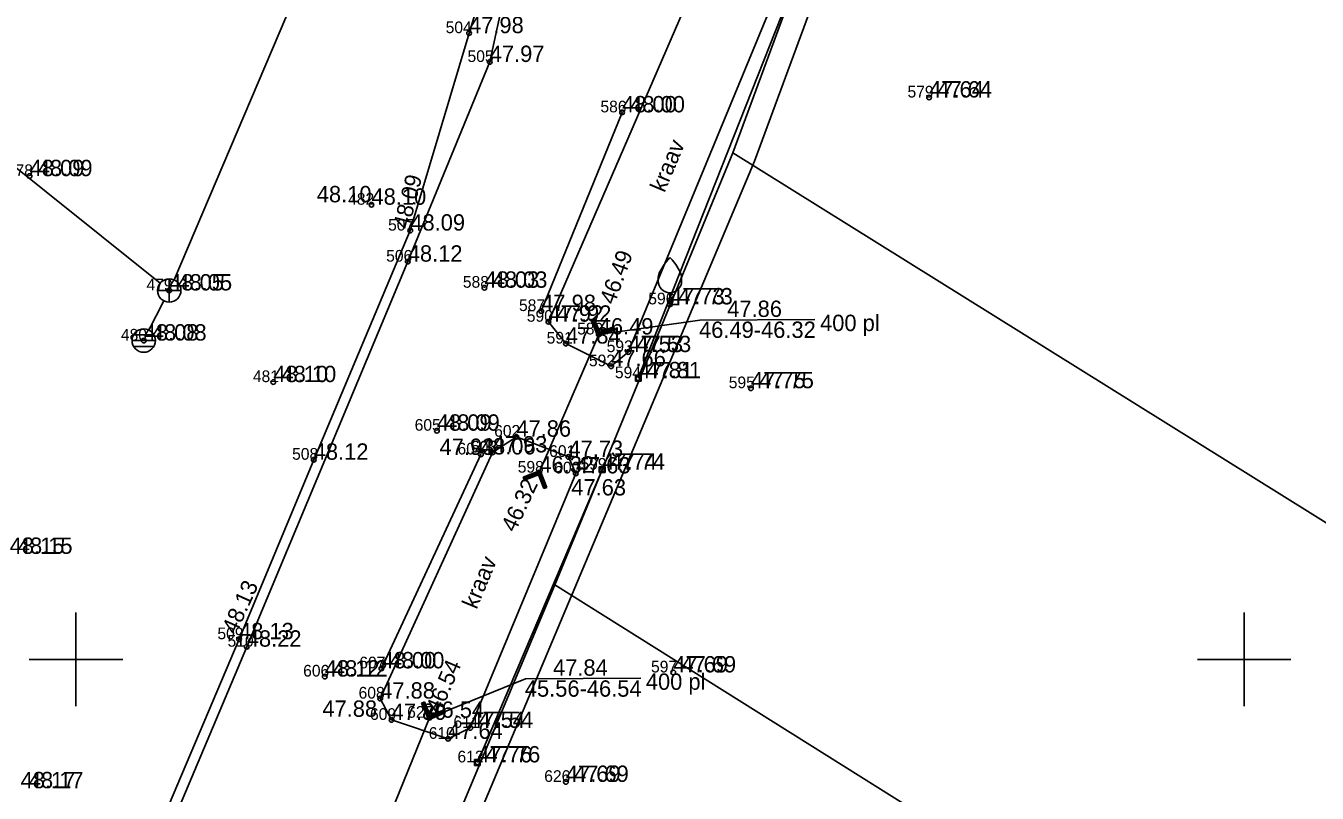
# Model space of a CAD drawing. Extents: x 640876 to 641418, y 6455595 to 6456085.
# Drawn here: x 641197.9 to 641253.1, y 6455944.3 to 6455977.1 of the extents above; entities that cross this region are included whole.
import ezdxf

# ---------------------------------------------------------------- set-up
doc = ezdxf.new("R2010")
doc.units = 0
for name, color, linetype in [('AED', 7, 'Continuous'), ('KKAEV', 7, 'Continuous'), ('KORGUS', 7, 'Continuous'), ('MOOTKORG', 7, 'Continuous'), ('MOOTMPUNKT', 7, 'Continuous'), ('MOOTNR', 7, 'Continuous'), ('MOOTPIIR', 7, 'Continuous'), ('PIIR', 7, 'Continuous'), ('PUU', 7, 'Continuous'), ('SKKAEV', 7, 'Continuous'), ('SKTRASS', 7, 'Continuous'), ('TEE', 7, 'Continuous'), ('TRUUP', 7, 'Continuous'), ('VEEKOGU', 7, 'Continuous'), ('VORK', 7, 'Continuous')]:
    doc.layers.add(name, color=color, linetype=linetype)

msp = doc.modelspace()

# ---------------------------------------------------------------- linework, layer by layer
at = {"layer": 'AED'}
for p, q in [((641223.94, 6455962.153), (641223.94, 6455961.903)), ((641223.94, 6455962.153), (641224.19, 6455962.153)), ((641223.94, 6455961.903), (641224.19, 6455961.903)), ((641224.19, 6455962.153), (641224.19, 6455961.903)), ((641222.394, 6455958.241), (641222.394, 6455957.991)), ((641222.394, 6455958.241), (641222.644, 6455958.241)), ((641222.644, 6455958.241), (641222.644, 6455957.991)), ((641222.394, 6455957.991), (641222.644, 6455957.991)), ((641217.053, 6455945.714), (641217.053, 6455945.464)), ((641217.053, 6455945.714), (641217.303, 6455945.714)), ((641217.053, 6455945.464), (641217.303, 6455945.464)), ((641217.303, 6455945.714), (641217.303, 6455945.464))]:
    msp.add_line(p, q, dxfattribs=at)
for points in [[(641160.606, 6455994.253), (641178.047, 6455995.168), (641191.652, 6455995.856), (641207.752, 6455996.687), (641222.341, 6455997.449), (641221.765, 6455994.718), (641219.959, 6455985.906), (641217.708, 6455975.561), (641214.2, 6455967.017), (641207.311, 6455950.541), (641202.719, 6455939.647), (641198.916, 6455930.446)], [(641231.229, 6455980.143), (641224.065, 6455962.028)], [(641222.519, 6455958.116), (641217.178, 6455945.589)]]:
    msp.add_lwpolyline(points, dxfattribs=at)
at = {"layer": 'KKAEV'}
for p, q in [((641203.491, 6455965.784), (641204.491, 6455965.784)), ((641203.991, 6455965.284), (641203.991, 6455966.284))]:
    msp.add_line(p, q, dxfattribs=at)
msp.add_circle((641203.991, 6455965.784), 0.5, dxfattribs=at)
at = {"layer": 'KORGUS'}
for centre in [(641236.513, 6455974.041), (641223.371, 6455973.405), (641198.016, 6455970.676), (641212.648, 6455969.453), (641214.309, 6455968.346), (641203.991, 6455965.784), (641217.483, 6455965.901), (641225.419, 6455965.189), (641220.221, 6455964.447), (641202.898, 6455963.64), (641222.374, 6455963.901), (641223.639, 6455963.147), (641208.446, 6455961.862), (641224.065, 6455962.028), (641228.888, 6455961.601), (641215.445, 6455959.783), (641217.83, 6455958.854), (641219.83, 6455957.988), (641221.392, 6455957.955), (641222.519, 6455958.116), (641206.979, 6455950.86), (641213.075, 6455949.614), (641210.648, 6455949.263), (641225.561, 6455949.439), (641213.02, 6455948.32), (641215.125, 6455947.499), (641216.876, 6455947.066), (641217.178, 6455945.589), (641220.966, 6455944.755)]:
    msp.add_circle(centre, 0.1, dxfattribs=at)
at = {"layer": 'MOOTMPUNKT'}
for centre in [(641216.822, 6455976.794), (641217.708, 6455975.561), (641236.513, 6455974.041), (641223.371, 6455973.405), (641198.016, 6455970.676), (641212.648, 6455969.453), (641214.309, 6455968.346), (641214.2, 6455967.017), (641203.991, 6455965.784), (641217.483, 6455965.901), (641225.419, 6455965.189), (641219.911, 6455964.904), (641220.221, 6455964.447), (641202.898, 6455963.64), (641220.969, 6455963.511), (641222.374, 6455963.901), (641223.639, 6455963.147), (641222.903, 6455962.539), (641208.446, 6455961.862), (641224.065, 6455962.028), (641228.888, 6455961.601), (641215.445, 6455959.783), (641218.847, 6455959.527), (641210.175, 6455958.541), (641217.328, 6455958.767), (641217.83, 6455958.854), (641221.076, 6455958.662), (641219.83, 6455957.988), (641221.392, 6455957.955), (641222.519, 6455958.116), (641206.979, 6455950.86), (641207.311, 6455950.541), (641213.075, 6455949.614), (641210.648, 6455949.263), (641225.561, 6455949.439), (641213.02, 6455948.32), (641213.509, 6455947.407), (641215.125, 6455947.499), (641216.876, 6455947.066), (641215.924, 6455946.598), (641217.178, 6455945.589), (641220.966, 6455944.755)]:
    msp.add_circle(centre, 0.1, dxfattribs=at)
at = {"layer": 'MOOTPIIR'}
msp.add_lwpolyline([(641060.916, 6455895.936), (641100.061, 6455950.482), (641099.586, 6455952.159), (641069.132, 6455984.035), (641066.132, 6455988.623), (641076.463, 6456005.049), (641230.642, 6456010.048), (641237.36, 6455995.24), (641237.24, 6455992.81), (641236.258, 6455990.888), (641229.041, 6455971.315), (641203.026, 6455909.57), (641225.257, 6455906.847), (641239.512, 6455898.491), (641200.195, 6455851.697), (641192.016, 6455859.099), (641169.785, 6455829.138), (641192.025, 6455807.568), (641252.96, 6455758.075), (641231.388, 6455736.74), (641191.474, 6455775.975), (641152.419, 6455787.914), (641136.351, 6455788.307), (641049.066, 6455856.043)], dxfattribs=at)
at = {"layer": 'PIIR'}
for points in [[(641222.58, 6455998.61), (641237.36, 6455995.24), (641235.34, 6455991.29), (641228.11, 6455971.68), (641220.5, 6455953.19), (641213.41, 6455936.25), (641201.58, 6455908.74), (641224.93, 6455905.88), (641191.87, 6455860.58), (641157.02, 6455885.66), (641160.91, 6455891.99), (641102.26, 6455951.82), (641074.95, 6455979.64), (641084.84, 6455991.92)], [(641301.94, 6455948.72), (641291.33, 6455932.26), (641228.11, 6455971.68), (641235.34, 6455991.29)], [(641280.77, 6455915.37), (641220.5, 6455953.19), (641228.11, 6455971.68), (641291.33, 6455932.26)], [(641270.69, 6455899.15), (641249.88, 6455902.84), (641253.51, 6455922.51), (641213.41, 6455936.25), (641220.5, 6455953.19), (641280.77, 6455915.37)]]:
    msp.add_lwpolyline(points, close=True, dxfattribs=at)
at = {"layer": 'PUU'}
for p, q in [((641225.419, 6455965.189), (641225.419, 6455965.689)), ((641225.819, 6455965.189), (641225.419, 6455965.189))]:
    msp.add_line(p, q, dxfattribs=at)
for points in [[(641223.371, 6455973.405), (641219.911, 6455964.904)], [(641224.919, 6455966.189), (641224.919, 6455966.339), (641224.929, 6455966.404), (641224.964, 6455966.534), (641225.024, 6455966.654), (641225.169, 6455966.889), (641225.329, 6455967.094), (641225.419, 6455967.189)], [(641225.919, 6455966.189), (641225.919, 6455966.339), (641225.909, 6455966.404), (641225.874, 6455966.534), (641225.814, 6455966.654), (641225.669, 6455966.889), (641225.509, 6455967.094), (641225.419, 6455967.189)], [(641217.328, 6455958.767), (641213.075, 6455949.614)]]:
    msp.add_lwpolyline(points, dxfattribs=at)
msp.add_arc((641225.419, 6455966.189), 0.5, 180, 0, dxfattribs=at)
at = {"layer": 'SKKAEV'}
for p, q in [((641202.398, 6455963.64), (641203.398, 6455963.64)), ((641203.328, 6455963.89), (641202.468, 6455963.89)), ((641203.328, 6455963.39), (641202.468, 6455963.39))]:
    msp.add_line(p, q, dxfattribs=at)
msp.add_circle((641202.898, 6455963.64), 0.5, dxfattribs=at)
at = {"layer": 'SKTRASS'}
for points in [[(641204.199, 6455966.239), (641213.185, 6455987.362)], [(641203.6, 6455966.097), (641191.18, 6455976.034)], [(641203.125, 6455964.086), (641203.764, 6455965.339)]]:
    msp.add_lwpolyline(points, dxfattribs=at)
at = {"layer": 'TEE'}
msp.add_lwpolyline([(641219.562, 6455985.852), (641216.822, 6455976.794), (641214.309, 6455968.346), (641210.175, 6455958.541), (641206.979, 6455950.86), (641202.453, 6455940.169), (641200.572, 6455935.729), (641195.267, 6455940.101), (641183.381, 6455949.957), (641172.174, 6455959.233), (641160.995, 6455968.496)], dxfattribs=at)
at = {"layer": 'TRUUP'}
for p, q in [((641222.176, 6455964.583), (641222.044, 6455964.53)), ((641222.044, 6455964.53), (641222.335, 6455963.808)), ((641222.071, 6455964.541), (641222.066, 6455964.476)), ((641222.097, 6455964.551), (641222.087, 6455964.424)), ((641222.123, 6455964.562), (641222.107, 6455964.373)), ((641222.11, 6455964.557), (641222.374, 6455963.901)), ((641222.149, 6455964.572), (641222.128, 6455964.321)), ((641222.175, 6455964.583), (641222.149, 6455964.27)), ((641222.196, 6455964.534), (641222.17, 6455964.218)), ((641222.176, 6455964.583), (641222.414, 6455963.993)), ((641222.217, 6455964.482), (641222.19, 6455964.167)), ((641222.238, 6455964.431), (641222.211, 6455964.115)), ((641222.258, 6455964.379), (641222.232, 6455964.064)), ((641222.279, 6455964.327), (641222.253, 6455964.012)), ((641222.3, 6455964.276), (641222.273, 6455963.961)), ((641222.321, 6455964.224), (641222.294, 6455963.909)), ((641222.341, 6455964.173), (641222.315, 6455963.858)), ((641222.335, 6455963.808), (641223.057, 6455964.099)), ((641222.362, 6455964.121), (641222.336, 6455963.809)), ((641222.374, 6455963.901), (641223.03, 6455964.165)), ((641222.414, 6455963.993), (641223.004, 6455964.231)), ((641222.635, 6455964.082), (641222.621, 6455963.924)), ((641222.661, 6455964.093), (641222.647, 6455963.934)), ((641222.687, 6455964.103), (641222.673, 6455963.944)), ((641222.713, 6455964.114), (641222.699, 6455963.955)), ((641222.739, 6455964.124), (641222.725, 6455963.965)), ((641222.765, 6455964.135), (641222.751, 6455963.976)), ((641222.791, 6455964.145), (641222.777, 6455963.986)), ((641222.817, 6455964.156), (641222.803, 6455963.997)), ((641222.843, 6455964.166), (641222.829, 6455964.007)), ((641222.869, 6455964.177), (641222.855, 6455964.018)), ((641222.894, 6455964.187), (641222.881, 6455964.028)), ((641222.92, 6455964.197), (641222.907, 6455964.039)), ((641222.946, 6455964.208), (641222.933, 6455964.049)), ((641222.972, 6455964.218), (641222.959, 6455964.06)), ((641222.998, 6455964.229), (641222.985, 6455964.07)), ((641223.004, 6455964.231), (641223.057, 6455964.099)), ((641223.02, 6455964.19), (641223.011, 6455964.08)), ((641223.041, 6455964.138), (641223.037, 6455964.091)), ((641222.383, 6455964.07), (641222.362, 6455963.819)), ((641222.404, 6455964.018), (641222.388, 6455963.829)), ((641222.427, 6455963.999), (641222.414, 6455963.84)), ((641222.453, 6455964.009), (641222.44, 6455963.85)), ((641222.479, 6455964.02), (641222.466, 6455963.861)), ((641222.505, 6455964.03), (641222.492, 6455963.871)), ((641222.531, 6455964.041), (641222.518, 6455963.882)), ((641222.557, 6455964.051), (641222.544, 6455963.892)), ((641222.583, 6455964.062), (641222.569, 6455963.903)), ((641222.609, 6455964.072), (641222.595, 6455963.913)), ((641219.871, 6455958.08), (641219.146, 6455957.795)), ((641219.647, 6455957.839), (641219.661, 6455957.998)), ((641219.673, 6455957.849), (641219.687, 6455958.008)), ((641219.699, 6455957.859), (641219.713, 6455958.018)), ((641219.725, 6455957.87), (641219.739, 6455958.028)), ((641219.751, 6455957.88), (641219.765, 6455958.039)), ((641219.777, 6455957.89), (641219.791, 6455958.049)), ((641219.8, 6455957.87), (641219.818, 6455958.059)), ((641219.82, 6455957.819), (641219.844, 6455958.069)), ((641219.841, 6455957.767), (641219.87, 6455958.08)), ((641219.861, 6455957.715), (641219.89, 6455958.03)), ((641220.156, 6455957.356), (641219.871, 6455958.08)), ((641219.198, 6455957.663), (641219.146, 6455957.795)), ((641219.162, 6455957.756), (641219.166, 6455957.803)), ((641219.83, 6455957.988), (641219.172, 6455957.729)), ((641219.182, 6455957.704), (641219.192, 6455957.813)), ((641219.79, 6455957.895), (641219.198, 6455957.663)), ((641219.204, 6455957.665), (641219.218, 6455957.823)), ((641219.23, 6455957.675), (641219.244, 6455957.834)), ((641219.256, 6455957.685), (641219.27, 6455957.844)), ((641219.282, 6455957.695), (641219.296, 6455957.854)), ((641219.308, 6455957.706), (641219.323, 6455957.864)), ((641219.334, 6455957.716), (641219.349, 6455957.875)), ((641219.36, 6455957.726), (641219.375, 6455957.885)), ((641219.386, 6455957.736), (641219.401, 6455957.895)), ((641219.412, 6455957.747), (641219.427, 6455957.905)), ((641219.438, 6455957.757), (641219.453, 6455957.916)), ((641219.464, 6455957.767), (641219.479, 6455957.926)), ((641219.49, 6455957.777), (641219.505, 6455957.936)), ((641219.516, 6455957.788), (641219.531, 6455957.946)), ((641219.542, 6455957.798), (641219.557, 6455957.957)), ((641219.568, 6455957.808), (641219.583, 6455957.967)), ((641219.594, 6455957.818), (641219.609, 6455957.977)), ((641219.62, 6455957.829), (641219.635, 6455957.987)), ((641220.023, 6455957.304), (641219.79, 6455957.895)), ((641220.089, 6455957.33), (641219.83, 6455957.988)), ((641219.881, 6455957.664), (641219.911, 6455957.979)), ((641219.902, 6455957.612), (641219.931, 6455957.927)), ((641219.922, 6455957.56), (641219.951, 6455957.875)), ((641219.942, 6455957.509), (641219.972, 6455957.824)), ((641219.963, 6455957.457), (641219.992, 6455957.772)), ((641219.983, 6455957.405), (641220.012, 6455957.72)), ((641220.003, 6455957.353), (641220.033, 6455957.668)), ((641220.024, 6455957.304), (641220.053, 6455957.617)), ((641220.05, 6455957.314), (641220.073, 6455957.565)), ((641220.076, 6455957.324), (641220.094, 6455957.513)), ((641220.102, 6455957.335), (641220.114, 6455957.462)), ((641220.023, 6455957.304), (641220.156, 6455957.356)), ((641220.128, 6455957.345), (641220.134, 6455957.41)), ((641214.919, 6455948.179), (641214.788, 6455948.125)), ((641214.788, 6455948.125), (641215.087, 6455947.406)), ((641214.815, 6455948.136), (641214.81, 6455948.071)), ((641214.841, 6455948.147), (641214.832, 6455948.019)), ((641214.867, 6455948.157), (641214.853, 6455947.968)), ((641214.853, 6455948.152), (641215.125, 6455947.499)), ((641214.892, 6455948.168), (641214.874, 6455947.917)), ((641214.918, 6455948.179), (641214.896, 6455947.866)), ((641214.94, 6455948.13), (641214.917, 6455947.814)), ((641214.919, 6455948.179), (641215.164, 6455947.592)), ((641214.961, 6455948.079), (641214.938, 6455947.763)), ((641214.982, 6455948.027), (641214.96, 6455947.712)), ((641215.004, 6455947.976), (641214.981, 6455947.66)), ((641215.025, 6455947.925), (641215.002, 6455947.609)), ((641215.047, 6455947.873), (641215.024, 6455947.558)), ((641215.068, 6455947.822), (641215.045, 6455947.507)), ((641215.089, 6455947.771), (641215.066, 6455947.455)), ((641215.087, 6455947.406), (641215.805, 6455947.705)), ((641215.111, 6455947.72), (641215.088, 6455947.407)), ((641215.132, 6455947.668), (641215.114, 6455947.417)), ((641215.125, 6455947.499), (641215.778, 6455947.771)), ((641215.153, 6455947.617), (641215.14, 6455947.428)), ((641215.164, 6455947.592), (641215.751, 6455947.837)), ((641215.177, 6455947.598), (641215.165, 6455947.439)), ((641215.203, 6455947.609), (641215.191, 6455947.45)), ((641215.229, 6455947.619), (641215.217, 6455947.46)), ((641215.254, 6455947.63), (641215.243, 6455947.471)), ((641215.28, 6455947.641), (641215.269, 6455947.482)), ((641215.306, 6455947.652), (641215.295, 6455947.493)), ((641215.332, 6455947.662), (641215.321, 6455947.503)), ((641215.358, 6455947.673), (641215.346, 6455947.514)), ((641215.384, 6455947.684), (641215.372, 6455947.525)), ((641215.41, 6455947.695), (641215.398, 6455947.536)), ((641215.435, 6455947.705), (641215.424, 6455947.546)), ((641215.461, 6455947.716), (641215.45, 6455947.557)), ((641215.487, 6455947.727), (641215.476, 6455947.568)), ((641215.513, 6455947.738), (641215.501, 6455947.579)), ((641215.539, 6455947.748), (641215.527, 6455947.589)), ((641215.565, 6455947.759), (641215.553, 6455947.6)), ((641215.59, 6455947.77), (641215.579, 6455947.611)), ((641215.616, 6455947.781), (641215.605, 6455947.622)), ((641215.642, 6455947.791), (641215.631, 6455947.632)), ((641215.668, 6455947.802), (641215.656, 6455947.643)), ((641215.694, 6455947.813), (641215.682, 6455947.654)), ((641215.72, 6455947.824), (641215.708, 6455947.665)), ((641215.746, 6455947.835), (641215.734, 6455947.676)), ((641215.751, 6455947.837), (641215.805, 6455947.705)), ((641215.768, 6455947.796), (641215.76, 6455947.686)), ((641215.789, 6455947.744), (641215.786, 6455947.697))]:
    msp.add_line(p, q, dxfattribs=at)
for points in [[(641231.625, 6455964.548), (641226.696, 6455964.518), (641222.374, 6455963.901)], [(641219.83, 6455957.988), (641222.374, 6455963.901)], [(641224.169, 6455949.196), (641219.239, 6455949.167), (641215.125, 6455947.499)], [(641215.125, 6455947.499), (641212.747, 6455941.628)]]:
    msp.add_lwpolyline(points, dxfattribs=at)
at = {"layer": 'VEEKOGU'}
for points in [[(641223.639, 6455963.147), (641230.651, 6455980.138), (641229.496, 6455980.913), (641227.432, 6455981.074), (641220.221, 6455964.447), (641220.969, 6455963.511), (641222.903, 6455962.539), (641223.639, 6455963.147)], [(641216.876, 6455947.066), (641221.392, 6455957.955), (641221.076, 6455958.662), (641218.847, 6455959.527), (641217.83, 6455958.854), (641213.02, 6455948.32), (641213.509, 6455947.407), (641215.924, 6455946.598), (641216.876, 6455947.066)]]:
    msp.add_lwpolyline(points, dxfattribs=at)
at = {"layer": 'VORK'}
for p, q in [((641200, 6455952), (641200, 6455948)), ((641250, 6455952), (641250, 6455948)), ((641198, 6455950), (641202, 6455950)), ((641248, 6455950), (641252, 6455950))]:
    msp.add_line(p, q, dxfattribs=at)

# ---------------------------------------------------------------- texts
at = {"layer": 'KORGUS'}
for s, p in [('47.64', (641236.863, 6455974.041)), ('48.00', (641223.721, 6455973.405)), ('48.09', (641198.366, 6455970.676)), ('48.10', (641210.306, 6455969.556)), ('48.05', (641204.341, 6455965.784)), ('48.03', (641217.833, 6455965.901)), ('47.73', (641225.769, 6455965.189)), ('47.92', (641220.571, 6455964.447)), ('48.08', (641203.248, 6455963.64)), ('47.53', (641223.989, 6455963.147)), ('48.10', (641208.796, 6455961.862)), ('47.81', (641224.415, 6455962.028)), ('47.75', (641229.238, 6455961.601)), ('48.09', (641215.795, 6455959.783)), ('47.93', (641215.561, 6455958.746)), ('47.74', (641222.869, 6455958.116)), ('47.63', (641221.198, 6455957.013)), ('48.15', (641197.512, 6455954.513)), ('48.00', (641213.425, 6455949.614)), ('48.12', (641210.998, 6455949.263)), ('47.69', (641225.911, 6455949.439)), ('47.88', (641210.545, 6455947.54)), ('47.54', (641217.226, 6455947.066)), ('47.76', (641217.528, 6455945.589)), ('47.69', (641221.316, 6455944.755)), ('48.17', (641197.982, 6455944.484))]:
    msp.add_text(s, height=0.7, dxfattribs=at).set_placement(p)
for s, rotation, p in [('48.09', 75.6003, (641214.238, 6455968.367)), ('46.49', 70.0088, (641223.044, 6455965.139)), ('46.32', 64.8841, (641218.795, 6455955.396)), ('48.13', 65.6585, (641206.855, 6455951.038)), ('46.54', 66.8951, (641215.588, 6455947.631))]:
    msp.add_text(s, height=0.7, rotation=rotation, dxfattribs=at).set_placement(p)
at = {"layer": 'MOOTKORG'}
for s, p in [('47.98', (641216.822, 6455976.794)), ('47.97', (641217.708, 6455975.561)), ('47.64', (641236.513, 6455974.041)), ('48.00', (641223.371, 6455973.405)), ('48.09', (641198.016, 6455970.676)), ('48.10', (641212.648, 6455969.453)), ('48.09', (641214.309, 6455968.346)), ('48.12', (641214.2, 6455967.017)), ('48.05', (641203.991, 6455965.784)), ('48.03', (641217.483, 6455965.901)), ('47.73', (641225.419, 6455965.189)), ('47.98', (641219.911, 6455964.904)), ('47.92', (641220.221, 6455964.447)), ('48.08', (641202.898, 6455963.64)), ('47.84', (641220.969, 6455963.511)), ('46.49', (641222.374, 6455963.901)), ('47.53', (641223.639, 6455963.147)), ('47.66', (641222.903, 6455962.539)), ('48.10', (641208.446, 6455961.862)), ('47.81', (641224.065, 6455962.028)), ('47.75', (641228.888, 6455961.601)), ('48.09', (641215.445, 6455959.783)), ('47.86', (641218.847, 6455959.527)), ('48.12', (641210.175, 6455958.541)), ('48.06', (641217.328, 6455958.767)), ('47.93', (641217.83, 6455958.854)), ('47.73', (641221.076, 6455958.662)), ('46.32', (641219.83, 6455957.988)), ('47.63', (641221.392, 6455957.955)), ('47.74', (641222.519, 6455958.116)), ('48.15', (641197.162, 6455954.513)), ('48.13', (641206.979, 6455950.86)), ('48.22', (641207.311, 6455950.541)), ('48.00', (641213.075, 6455949.614)), ('48.12', (641210.648, 6455949.263)), ('47.69', (641225.561, 6455949.439)), ('47.88', (641213.02, 6455948.32)), ('47.80', (641213.509, 6455947.407)), ('46.54', (641215.125, 6455947.499)), ('47.54', (641216.876, 6455947.066)), ('47.64', (641215.924, 6455946.598)), ('47.76', (641217.178, 6455945.589)), ('47.69', (641220.966, 6455944.755)), ('48.17', (641197.632, 6455944.484))]:
    msp.add_text(s, height=0.7, dxfattribs=at).set_placement(p)
at = {"layer": 'MOOTNR'}
for s, p in [('504', (641215.822, 6455976.794)), ('505', (641216.758, 6455975.561)), ('579', (641235.588, 6455974.041)), ('586', (641222.446, 6455973.405)), ('478', (641197.041, 6455970.676)), ('482', (641211.648, 6455969.453)), ('507', (641213.359, 6455968.346)), ('506', (641213.275, 6455967.017)), ('479', (641203.016, 6455965.784)), ('588', (641216.558, 6455965.901)), ('587', (641218.961, 6455964.904)), ('596', (641224.494, 6455965.189)), ('590', (641219.296, 6455964.447)), ('480', (641201.923, 6455963.64)), ('589', (641221.449, 6455963.901)), ('591', (641220.144, 6455963.511)), ('593', (641222.714, 6455963.147)), ('592', (641221.953, 6455962.539)), ('594', (641223.065, 6455962.028)), ('481', (641207.571, 6455961.862)), ('595', (641227.938, 6455961.601)), ('605', (641214.495, 6455959.783)), ('602', (641217.897, 6455959.527)), ('604', (641216.329, 6455958.767)), ('603', (641216.905, 6455958.854)), ('601', (641220.251, 6455958.662)), ('508', (641209.25, 6455958.541)), ('599', (641221.594, 6455958.116)), ('598', (641218.906, 6455957.988)), ('600', (641220.468, 6455957.955)), ('509', (641206.054, 6455950.86)), ('510', (641206.486, 6455950.541)), ('606', (641209.723, 6455949.263)), ('607', (641212.125, 6455949.614)), ('597', (641224.611, 6455949.439)), ('608', (641212.095, 6455948.32)), ('609', (641212.584, 6455947.407)), ('627', (641214.175, 6455947.499)), ('611', (641216.151, 6455947.066)), ('610', (641215.099, 6455946.598)), ('612', (641216.328, 6455945.589)), ('626', (641220.041, 6455944.755))]:
    msp.add_text(s, height=0.5, dxfattribs=at).set_placement(p)
at = {"layer": 'TRUUP'}
for s, p in [('47.86', (641227.873, 6455964.651)), ('400 pl', (641231.846, 6455964.047)), ('46.49-46.32', (641226.666, 6455963.753)), ('47.84', (641220.416, 6455949.299)), ('400 pl', (641224.389, 6455948.696)), ('45.56-46.54', (641219.21, 6455948.401))]:
    msp.add_text(s, height=0.7, dxfattribs=at).set_placement(p)
at = {"layer": 'VEEKOGU'}
for p in [(641225.189, 6455969.94), (641217.145, 6455952.109)]:
    msp.add_text('kraav', height=0.7, rotation=67.3204, dxfattribs=at).set_placement(p)

doc.saveas('drawing.dxf')
